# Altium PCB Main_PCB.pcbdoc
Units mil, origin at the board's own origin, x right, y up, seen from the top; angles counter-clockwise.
Board outline 4486.01 x 2606.73 mil, 2 copper layers (Top Layer, Bottom Layer); 37 components, 31 nets, 178 pads, 21 vias.
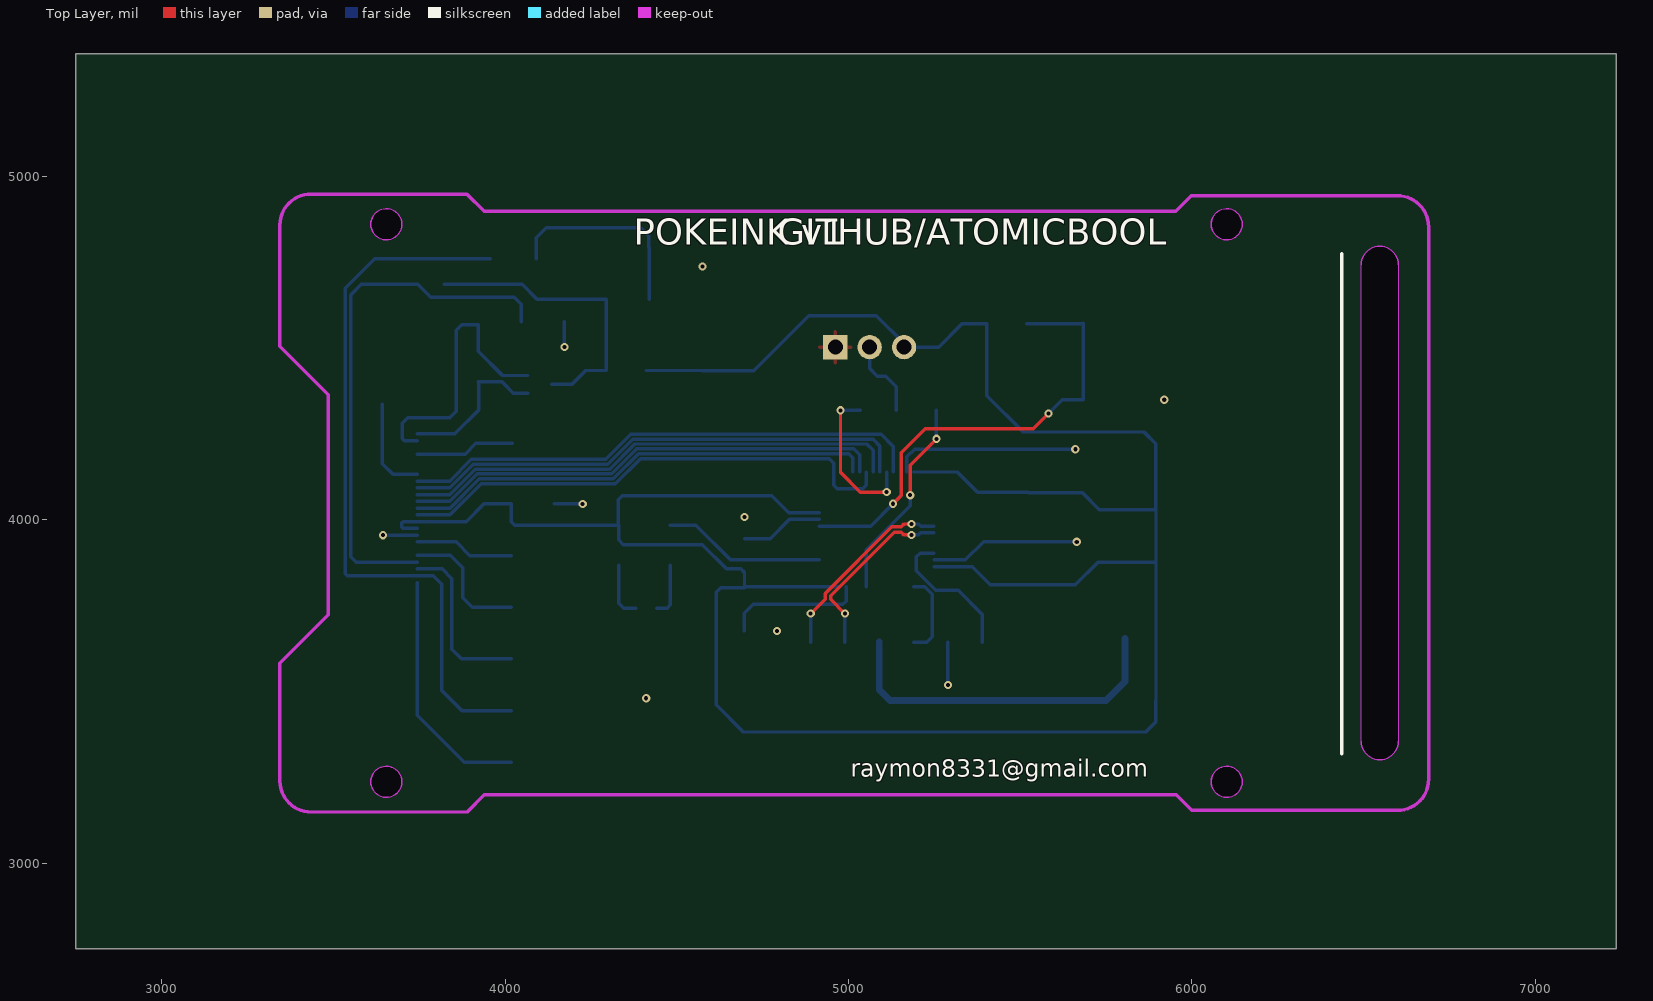
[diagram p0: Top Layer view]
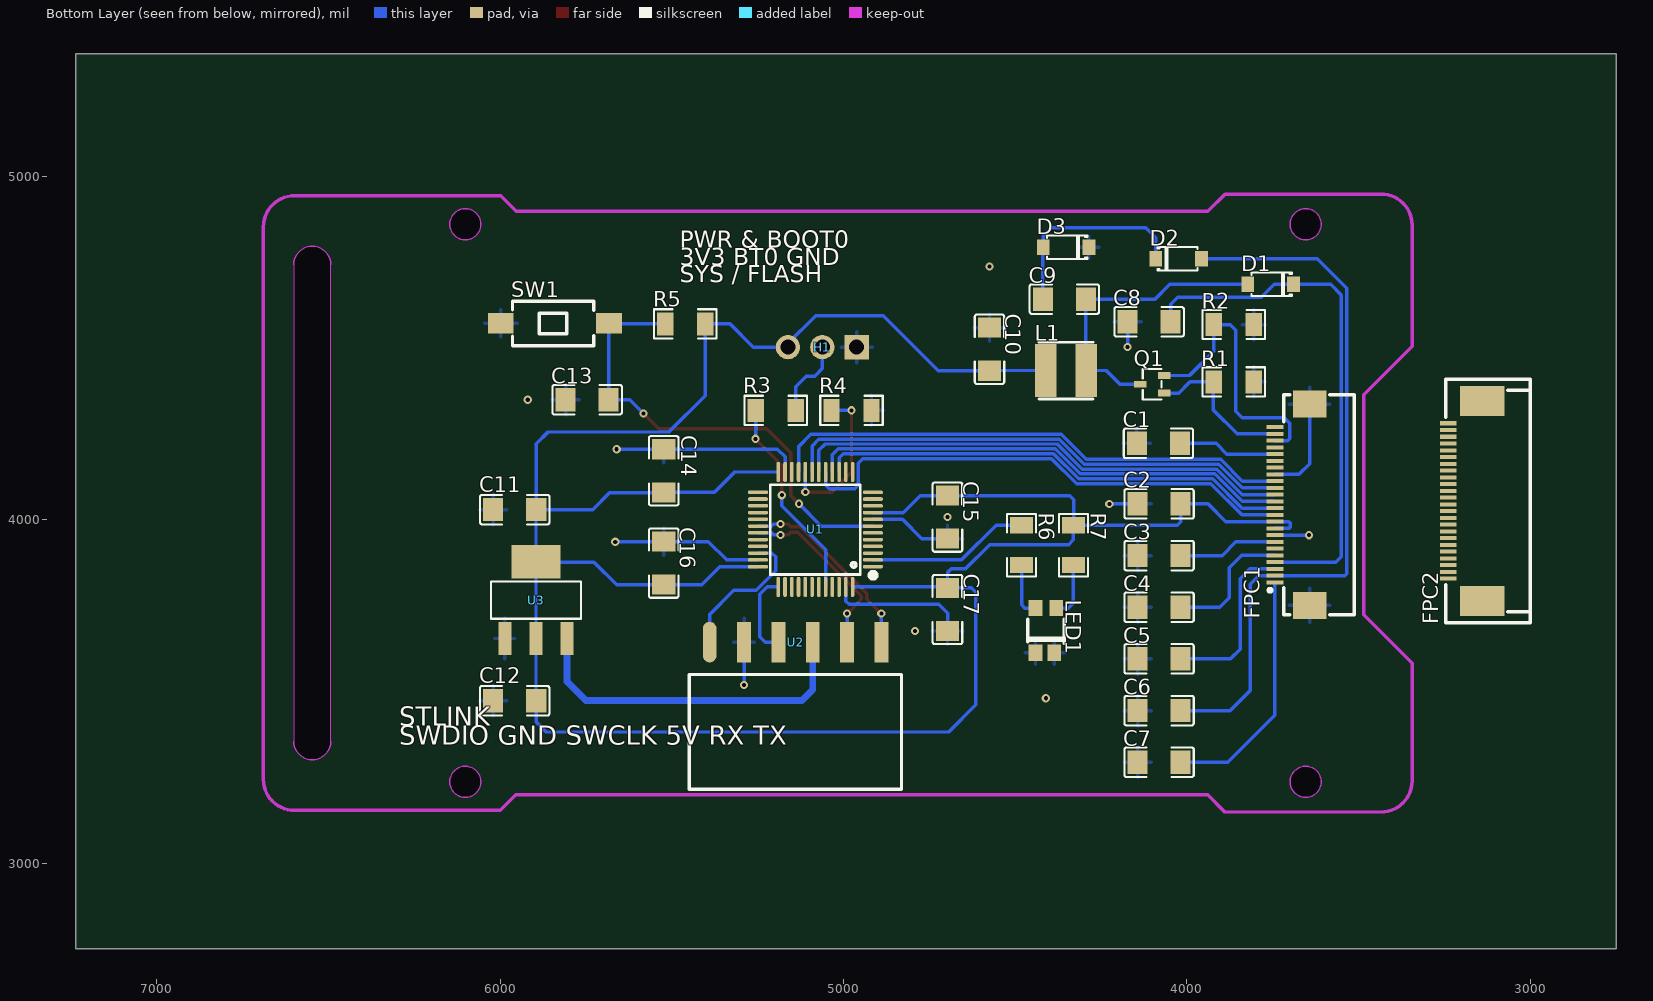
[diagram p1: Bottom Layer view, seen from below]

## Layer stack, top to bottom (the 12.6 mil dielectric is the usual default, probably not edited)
Top Layer: signal copper (thickness not stored)
Dielectric: dielectric 12.6, FR-4, Dk 4.8
Bottom Layer: signal copper (thickness not stored)

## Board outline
7236.01,2750 2750,2750 2750,5356.73 7236.01,5356.73
cut-out: 3699.25,4860.64 cw(c3653.98,4860.64) 3608.7,4860.64 cw(c3653.98,4860.64)
cut-out: 3699.25,3236.64 cw(c3653.98,3236.64) 3608.7,3236.64 cw(c3653.98,3236.64)
cut-out: 6147.24,4860.64 cw(c6101.96,4860.64) 6056.69,4860.64 cw(c6101.96,4860.64)
cut-out: 6147.24,3236.64 cw(c6101.96,3236.64) 6056.69,3236.64 cw(c6101.96,3236.64)
cut-out: 6547.71,4796.67 cw(c6547.71,4742.54) 6601.85,4742.54 6601.85,3354.74 cw(c6547.71,3354.74) 6547.71,3300.61 cw(c6547.71,3354.74) 6493.58,3354.74 6493.58,4742.54 cw(c6547.71,4742.54)

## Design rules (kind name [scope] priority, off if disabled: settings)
BoardOutlineClearance copperThickness1oz [All] p0: genericclearance=10 ignorepadtopadclearanceinfootprint=FALSE except(0: Arc-SplitContinuation Track-SplitContinuation SMDPad-SplitContinuation THPad-SplitContinuation Via-SplitContinuation Fill-SplitContinuation Poly-SplitContinuation Region-SplitContinuation Text-SplitContinuation; 6: Track-CutoutEdge SMDPad-CutoutEdge THPad-CutoutEdge Via-CutoutEdge Region-CutoutEdge; 11.8: Track-OutlineEdge SMDPad-OutlineEdge THPad-OutlineEdge Via-OutlineEdge Fill-OutlineEdge Region-OutlineEdge Poly-OutlineEdge Text-OutlineEdge Fill-CutoutEdge)
BoardOutlineClearance copperThickness2oz [All] p0: genericclearance=10 ignorepadtopadclearanceinfootprint=FALSE except(0: Arc-SplitContinuation Track-SplitContinuation SMDPad-SplitContinuation THPad-SplitContinuation Via-SplitContinuation Fill-SplitContinuation Poly-SplitContinuation Region-SplitContinuation Text-SplitContinuation; 6: Track-CutoutEdge SMDPad-CutoutEdge THPad-CutoutEdge Via-CutoutEdge Region-CutoutEdge; 11.8: Track-OutlineEdge SMDPad-OutlineEdge THPad-OutlineEdge Via-OutlineEdge Fill-OutlineEdge Region-OutlineEdge Poly-OutlineEdge Text-OutlineEdge Fill-CutoutEdge)
Clearance copperThickness1oz [(InNet('VCOM') OR InNet('PVGL') OR InNet('$1N1662') OR InNet('PVGH') OR InNet('$1N1618') OR InNet('$1N1584') OR InNet('GND') OR InNet('3V3') OR InNet('CS') OR InNet('DCX') OR InNet('RES') OR InNet('BUSY') OR InNet('$1N1465') OR InNet('RESE') OR InNet('GDR') OR InNet('$1N1889') OR InNet('$1N2921') OR InNet('NRST') OR InNet('BOOT1') OR InNet('BOOT0') OR InNet('$1N4223') OR InNet('5V') OR InNet('SDA') OR InNet('SCK') OR InNet('USART_TX') OR InNet('USART_RX') OR InNet('SWDIO') OR InNet('SWCLK') OR InNet('LED_MCU') OR InNet('$1N6084') OR InNet('$1N6080'))] p1: gap=7 ignorepadtopadclearanceinfootprint=FALSE except(4: Track-Track; 6: Track-SMDPad SMDPad-SMDPad Track-THPad SMDPad-THPad THPad-THPad Track-Via SMDPad-Via THPad-Via Via-Via SMDPad-Fill THPad-Fill Via-Fill Fill-Fill Track-Region SMDPad-Region THPad-Region Via-Region Region-Region Track-Poly SMDPad-Poly THPad-Poly Via-Poly Fill-Poly Region-Poly Poly-Poly Track-Text SMDPad-Text THPad-Text Via-Text Fill-Text Region-Text Poly-Text Text-Text; 6.9: Track-Hole SMDPad-Hole THPad-Hole Via-Hole Fill-Hole Region-Hole Poly-Hole Text-Hole Sheet-Hole; 11.8: Track-Fill Fill-Region Track-Sheet SMDPad-Sheet THPad-Sheet Via-Sheet Fill-Sheet Region-Sheet Poly-Sheet Text-Sheet)
Clearance copperThickness2oz [All] p1: gap=7 ignorepadtopadclearanceinfootprint=FALSE except(6: Track-SMDPad SMDPad-SMDPad Track-THPad SMDPad-THPad THPad-THPad Track-Via SMDPad-Via THPad-Via Via-Via SMDPad-Fill THPad-Fill Via-Fill Fill-Fill Track-Region SMDPad-Region THPad-Region Via-Region Region-Region Track-Poly SMDPad-Poly THPad-Poly Via-Poly Fill-Poly Region-Poly Poly-Poly Track-Text SMDPad-Text THPad-Text Via-Text Fill-Text Region-Text Poly-Text Text-Text; 6.9: Track-Hole SMDPad-Hole THPad-Hole Via-Hole Fill-Hole Region-Hole Poly-Hole Text-Hole Sheet-Hole; 8: Track-Track; 11.8: Track-Fill Fill-Region Track-Sheet SMDPad-Sheet THPad-Sheet Via-Sheet Fill-Sheet Region-Sheet Poly-Sheet Text-Sheet)
DiffPairsRouting differentialPair [All] p1: maxuncoupledlength=200 minlimit=6 maxlimit=6 mostfreqgap=6 toplayer_minwidth=5 toplayer_prefwidth=10 toplayer_maxwidth=100 bottomlayer_minwidth=5 bottomlayer_prefwidth=10 bottomlayer_maxwidth=100
PasteMaskExpansion pasteMaskExpansion [All] p1: expansion=0
PlaneConnect innerPlane [All] p1: planeconnectstyle=Relief reliefexpansion=20 reliefentries=4 reliefconductorwidth=10 reliefairgap=10
PolygonConnect copperRegion [All] p1: connectstyle=Relief reliefentries=4 reliefconductorwidth=10 polygonreliefangle="90 Angle" airgapwidth=10
RoutingVias viaSize [All] p1: viastyle="Through Hole" holewidth=12.0078 minholewidth=11.811 maxholewidth=248.0314 width=24.0158 minwidth=19.685 maxwidth=393.7008
SolderMaskExpansion solderMaskExpansion [All] p1: useseparateexpansions=TRUE expansion=2 expansionbottom=2
Width copperThickness1oz [All] p1: maxlimit=100 minlimit=5 preferedwidth=10
Width copperThickness2oz [All] p1: maxlimit=100 minlimit=8 preferedwidth=10

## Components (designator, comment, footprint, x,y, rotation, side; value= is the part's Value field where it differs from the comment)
C1 "CL31B105KAHNNNE" C1206 4082.98,4222.64 r180 bottom
C2 "CL31B105KAHNNNE" C1206 4080.98,4046.14 r0 bottom
C3 "CL31B105KAHNNNE" C1206 4080.98,3895.64 r0 bottom
C4 "CL31B105KAHNNNE" C1206 4080.98,3745.14 r0 bottom
C5 "CL31B105KAHNNNE" C1206 4080.98,3594.64 r0 bottom
C6 "CL31B105KAHNNNE" C1206 4080.98,3444.14 r0 bottom
C7 "CL31B105KAHNNNE" C1206 4080.98,3293.64 r0 bottom
C8 "CL31B105KAHNNNE" C1206 4109.98,4576.64 r180 bottom
C9 "1206B475K250NT" C1206 4356.98,4642.64 r0 bottom
C10 "1206B475K250NT" C1206 4574.98,4496.64 r90 bottom
C11 "CL31B104KCFNNNE" C1206 5957.98,4029.64 r180 bottom
C12 "CL31B104KCFNNNE" C1206 5957.98,3472.64 r180 bottom
C13 "CL31B104KCFNNNE" C1206 5746.98,4349.64 r0 bottom
C14 "CL31B104KCFNNNE" C1206 5523.98,4142.64 r270 bottom
C15 "CL31B104KCFNNNE" C1206 4697.39,4007.64 r90 bottom
C16 "CL31B104KCFNNNE" C1206 5523.98,3873.64 r270 bottom
C17 "CL31B104KCFNNNE" C1206 4697.39,3738.64 r270 bottom
D1 "MBR0530_C77336" SOD-123_L2.8-W1.8-LS3.7-RD 3755.98,4685.64 r0 bottom
D2 "MBR0530_C77336" SOD-123_L2.8-W1.8-LS3.7-RD 4023.98,4760.64 r180 bottom
D3 "MBR0530_C77336" SOD-123_L2.8-W1.8-LS3.7-RD 4351.98,4793.64 r0 bottom
FPC1 "FPC-05F-24PH20" FPC-SMD_24P-P0.50_FPC-05F-24PH20 3692.98,4043.64 r90 bottom
FPC2 "AFC07-S24ECA-00" FPC-SMD_AFC07-S24ECA-00 3188.98,4054.64 r90 bottom
H1 "PZ254R-11-03P" HDR-TH_3P-P2.54-H-M-W10.4 5061.98,4502.64 r0 bottom
L1 "FNR4020S680MT" IND-SMD_L4.0-W4.0_FNR40XXS 4351.98,4434.64 r180 bottom
LED1 "TJ-S3227SW1TCGLC2R6B-A5" LED-SMD_4P-L3.2-W2.7_PD15-22C 4410.98,3677.64 r90 bottom
Q1 "SI1308EDL" SOT-323-3_L2.0-W1.3-P1.30-LS2.1-BR 4100.98,4394.64 r180 bottom
R1 "FRC1206J105 TS" R1206 3863.92,4401.64 r0 bottom
R2 "FRC1206J2R2 TS" R1206 3863.92,4568.37 r0 bottom
R3 "FRC1206J103 TS" R1206 5197.98,4318.64 r180 bottom
R4 "FRC1206J103 TS" R1206 4976.98,4318.64 r180 bottom
R5 "FRC1206J103 TS" R1206 5460.98,4570.64 r180 bottom
R6 "FRC1206J102 TS" R1206 4481.48,3926.14 r270 bottom
R7 "FRC1206J102 TS" R1206 4330.48,3926.14 r270 bottom
SW1 "TS-1101-C-W" SW-SMD_L6.0-W3.3-LS8.0 5840.98,4572.64 r180 bottom
U1 "STM32F103C8T6" LQFP-48_L7.0-W7.0-P0.50-LS9.0-BL 5081.98,3971.64 r90 bottom
U2 "HX PM2.54-1x6P WT" HDR-SMD_6P-P2.54-H-F-W11.7 5139.98,3643.64 r180 bottom
U3 "AMS1117-3.3_C347222" SOT-223-4_L6.5-W3.5-P2.30-LS7.0-BR 5895.98,3765.64 r270 bottom

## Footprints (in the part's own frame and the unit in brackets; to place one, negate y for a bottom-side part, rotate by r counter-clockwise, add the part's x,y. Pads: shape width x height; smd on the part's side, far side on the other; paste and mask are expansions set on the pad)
C1206 [mm]
  rect 1.485x1.728 smd: 1(-1.593,0) 2(1.593,0)
  silkscreen extent -2.56,-1.09 2.56,1.09
FPC-SMD_24P-P0.50_FPC-05F-24PH20 [mm]
  rect 0.3x1.25 smd: 1(5.75,1.288) 2(5.25,1.288) 3(4.75,1.288) 4(4.25,1.288) 5(3.75,1.288) 6(3.25,1.288) 7(2.75,1.288) 8(2.25,1.288) 9(1.75,1.288) 10(1.25,1.288) 11(0.75,1.288) 12(0.25,1.288) 13(-0.25,1.288) 14(-0.75,1.288) 15(-1.25,1.288) 16(-1.75,1.288) 17(-2.25,1.288) 18(-2.75,1.288) 19(-3.25,1.288) 20(-3.75,1.288) 21(-4.25,1.288) 22(-4.75,1.288) 23(-5.25,1.288) 24(-5.75,1.288)
  rect 2x2.5 smd: 25(7.44,-1.288) 26(-7.44,-1.288)
  silkscreen extent -8.13,-4.57 8.13,1.78
FPC-SMD_AFC07-S24ECA-00 [mm]
  rect 0.3x1.2 smd: 1(5.75,1.266) 2(5.251,1.266) 3(4.75,1.266) 4(4.25,1.266) 5(3.75,1.266) 6(3.249,1.266) 7(2.749,1.266) 8(2.25,1.266) 9(1.751,1.266) 10(1.25,1.266) 11(0.75,1.266) 12(0.25,1.266) 13(-0.251,1.266) 14(-0.75,1.266) 15(-1.25,1.266) 16(-1.749,1.266) 17(-2.25,1.266) 18(-2.75,1.266) 19(-3.251,1.266) 20(-3.751,1.266) 21(-4.251,1.266) 22(-4.749,1.266) 23(-5.25,1.266) 24(-5.75,1.266)
  rect 2.2x3.3 smd: 25(-7.401,-1.266) 26(7.401,-1.259)
  silkscreen extent -9,-4.8 9,1.46
HDR-SMD_6P-P2.54-H-F-W11.7 [mm]
  oval 1.02x3 smd: 1(-6.35,0)
  rect 1.02x3 smd: 2(-3.81,0) 3(-1.27,0) 4(1.27,0) 5(3.81,0) 6(6.35,0)
  silkscreen extent -7.87,-10.9 7.84,-2.4
HDR-TH_3P-P2.54-H-M-W10.4 [mm]
  rect 1.8x1.8 hole 1.1: 1(-2.54,0)
  round 1.8 hole 1.1: 2(0,0) 3(2.54,0)
IND-SMD_L4.0-W4.0_FNR40XXS [mm]
  rect 1.6x3.9 smd: 1(-1.5,0) 2(1.5,0)
  silkscreen extent -2,-2.1 2,2.1
LED-SMD_4P-L3.2-W2.7_PD15-22C [mm]
  rect 1.2x1 smd: 1(-1.65,-0.636) 2(1.65,-0.763) 3(1.65,0.764) 4(-1.65,0.764)
  silkscreen extent -0.97,-1.35 0.84,1.35
LQFP-48_L7.0-W7.0-P0.50-LS9.0-BL [mm]
  oval 0.27x1.5 smd: 1(-2.75,-4.25) 2(-2.25,-4.25) 3(-1.75,-4.25) 4(-1.25,-4.25) 5(-0.75,-4.25) 6(-0.25,-4.25) 7(0.25,-4.25) 8(0.75,-4.25) 9(1.25,-4.25) 10(1.75,-4.25) 11(2.25,-4.25) 12(2.75,-4.25) 25(2.75,4.25) 26(2.25,4.25) 27(1.75,4.25) 28(1.25,4.25) 29(0.75,4.25) 30(0.25,4.25) 31(-0.25,4.25) 32(-0.75,4.25) 33(-1.25,4.25) 34(-1.75,4.25) 35(-2.25,4.25) 36(-2.75,4.25)
  oval 1.5x0.27 smd: 13(4.25,-2.75) 14(4.25,-2.25) 15(4.25,-1.75) 16(4.25,-1.25) 17(4.25,-0.75) 18(4.25,-0.25) 19(4.25,0.25) 20(4.25,0.75) 21(4.25,1.25) 22(4.25,1.75) 23(4.25,2.25) 24(4.25,2.75) 37(-4.25,2.75) 38(-4.25,2.25) 39(-4.25,1.75) 40(-4.25,1.25) 41(-4.25,0.75) 42(-4.25,0.25) 43(-4.25,-0.25) 44(-4.25,-0.75) 45(-4.25,-1.25) 46(-4.25,-1.75) 47(-4.25,-2.25) 48(-4.25,-2.75)
  silkscreen extent -3.59,-4.46 3.3,3.34
R1206 [mil]
  rect 47.54x66.97 smd: 1(-58.22,0) 2(58.22,0)
  silkscreen extent -91,-42 91,42
SOD-123_L2.8-W1.8-LS3.7-RD [mm]
  rect 0.95x1.15 smd: 1(-1.692,0) 2(1.692,0)
  silkscreen extent -1.58,-0.87 1.41,0.87
SOT-223-4_L6.5-W3.5-P2.30-LS7.0-BR [mm]
  rect 2.47x0.98 smd: 1(2.835,-2.3) 2(2.835,0) 3(2.835,2.3)
  rect 2.47x3.6 smd: 4(-2.835,0)
  silkscreen extent -1.37,-3.33 1.37,3.33
SOT-323-3_L2.0-W1.3-P1.30-LS2.1-BR [mm]
  rect 0.936x0.5 smd: 1(0.898,-0.65) 2(0.898,0.65) 3(-0.898,0)
  silkscreen extent -0.7,-1.13 0.7,1.13
SW-SMD_L6.0-W3.3-LS8.0 [mm]
  rect 1.9x1.5 smd: 1(-4,0) 2(4,0)
  silkscreen extent -3.14,-1.67 2.86,1.63

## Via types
v1: diameter 24.02, hole 12.01, Top Layer to Bottom Layer, 21 vias

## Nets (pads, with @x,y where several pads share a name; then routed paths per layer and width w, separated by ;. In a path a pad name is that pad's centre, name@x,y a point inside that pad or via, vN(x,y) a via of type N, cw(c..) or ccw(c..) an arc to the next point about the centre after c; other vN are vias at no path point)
3V3: C2.1 C10.1 C11.2 C12.2 C14.2 C15.2 C16.2 C17.1 FPC1.15 FPC1.16 H1.3 L1.1 R5.2 R7.1 U1.9 U1.24 U1.36 U1.48 U3.2 U3.4 | length 8115.3
  Bottom Layer w10: FPC1.16@3743.99,3974.73 3701.88,3974.73 3698.98,3977.64 3698.98,3990.64 3702.76,3994.42 FPC1.15 3886.76,3994.42 3938.48,4046.14 C2.1 4017.98,4045.84 4017.98,3994.64 4028.26,3984.36 R7.1 ; L1.1 4574.28,4434.64 C10.1 4724.28,4433.94 4884.98,4594.64 5080.98,4594.64 5161.98,4513.64 H1.3 5262.98,4502.64 5330.98,4570.64 R5.2 5402.98,4570.42 5402.98,4361.64 5508.98,4255.64 5860.98,4255.64 5895.28,4221.34 C11.2 ; U1.9 4826.77,4020.85 4777.28,4070.34 C15.2 4341.68,4070.34 4329.98,4058.64 4329.98,3984.86 R7.1 ; U1.48 4700.37,3804.32 C17.1 ; U1.24 5316.66,4138.96 5375.98,4079.64 5523.68,4079.64 C14.2 5525.28,4078.64 5681.98,4078.64 5730.98,4029.64 C11.2 ; U1.36 5360.25,3863.37 5412.68,3810.94 C16.2 5661.28,3810.94 5726.98,3876.64 5895.37,3876.64 U3.4 ; R7.1 4330.48,3941.14 4343.98,3927.64 4573.98,3927.64 4644.98,3856.64 4686.98,3856.64 4697.39,3846.23 C17.1 ; C17.1 4627.68,3801.34 4614.98,3788.64 4614.98,3460.64 4693.98,3381.64 5865.98,3381.64 5895.28,3410.94 C12.2 5895.98,3473.34 U3.2 U3.4 ; C11.2 5895.98,4028.94 U3.4
5V: U2.4 U3.3 | length 1015.8
  Bottom Layer w20: U2.4 5089.98,3504.64 5120.98,3473.64 5750.98,3473.64 5805.43,3528.09 U3.3
$1N1465: C1.2 FPC1.5 | length 289.3
  Bottom Layer w10: FPC1.5@3743.99,4191.27 3883.61,4191.27 3914.98,4222.64 C1.2
$1N1584: C3.1 FPC1.18 | length 290.7
  Bottom Layer w10: FPC1.18@3743.99,3935.36 3857.25,3935.36 3896.98,3895.64 C3.1
$1N1618: C4.1 FPC1.20 | length 387.7
  Bottom Layer w10: FPC1.20@3743.99,3895.99 3840.62,3895.99 3876.98,3859.64 3876.98,3772.64 3904.48,3745.14 C4.1
$1N1662: C5.1 FPC1.22 | length 503.5
  Bottom Layer w10: FPC1.22@3744,3856.64 3816.98,3856.64 3844.98,3828.64 3844.98,3622.64 3872.98,3594.64 C5.1
$1N1889: C9.2 D2.1 D3.2 | length 595.4
  Bottom Layer w10: D2.1 4090.61,4821.27 4119.98,4850.64 4394.98,4850.64 4418.61,4827.01 D3.2 4419.68,4792.57 C9.2
$1N2921: C9.1 D1.2 L1.2 Q1.3 | length 871.2
  Bottom Layer w10: D1.2 4049.98,4685.64 4092.98,4642.64 C9.1 4294.28,4436 L1.2 4234.98,4434.64 4194.98,4394.64 Q1.3
$1N4223: H1.2 R3.2 | length 230.3
  Bottom Layer w10: H1.2 5061.98,4440.64 5084.25,4418.36 5108.25,4418.36 5139.76,4386.86 R3.2
$1N6080: LED1.2 R7.2 | length 167.2
  Bottom Layer w10: R7.2 4330.98,3867.42 4330.98,3756.64 4345.02,3742.6 LED1.2
$1N6084: LED1.3 R6.2 | length 160.1
  Bottom Layer w10: LED1.3 4471.94,3742.6 ; 4471.98,3742.64 4481.48,3752.14 R6.2
BOOT0: R3.1 U1.44 | length 599.4
  Top Layer w10: v1(5179.98,4071.64) 5179.98,4158.64 v1(5256.98,4235.64)
  Bottom Layer w10: U1.44 5052.45,3913.11 5179.98,4040.64 v1(5179.98,4071.64) ; R3.1 5256.2,4236.42 v1(5256.98,4235.64)
BOOT1: R4.1 U1.20 | length 453.1
  Top Layer w10: v1(4976.98,4318.64) 4976.98,4138.64 5034.98,4080.64 v1(5111.51,4080.64)
  Bottom Layer w10: v1@4978.98,4318.64 R4.1 ; v1(5111.51,4080.64) U1.20
BUSY: FPC1.9 U1.21 | length 1532.6
  Bottom Layer w10: FPC1.9@3743.99,4112.53 3838.87,4112.53 3901.98,4175.64 4292.98,4175.64 4365.98,4248.64 5095.98,4248.64 5131.19,4213.43 U1.21
CS: FPC1.12 U1.16 | length 1410
  Bottom Layer w10: FPC1.12@3743.99,4053.47 3839.27,4053.47 3919.39,4133.59 4310.39,4133.59 4383.39,4206.59 5015.98,4206.59 5032.77,4189.8 U1.16
DCX: FPC1.11 U1.18 | length 1460.2
  Bottom Layer w10: FPC1.11@3743.99,4073.16 3839.14,4073.16 3913.59,4147.61 4304.59,4147.61 4377.59,4220.61 5053.98,4220.61 5072.14,4202.45 U1.18
GDR: FPC1.2 Q1.1 R1.2 | length 447
  Bottom Layer w10: FPC1.2@3743.99,4250.33 3853.67,4250.33 3922.98,4319.64 3922.98,4400.8 R1.2 3990.98,4401.64 4023.57,4369.05 Q1.1
GND: C1.1 C2.2 C3.2 C4.2 C5.2 C6.2 C7.2 C8.1 C10.2 C11.1 C12.1 C13.2 C14.1 C15.1 C16.1 C17.2 D3.1 FPC1.8 FPC1.17 FPC1.25 FPC1.26 H1.1 LED1.1 LED1.4 R1.1 R2.1 R4.2 SW1.1 U1.8 U1.23 U1.35 U1.47 U2.2 U3.1 | length 2295.4
  Bottom Layer w10: FPC1.25@3642.61,4336.55 3641.98,4335.92 3641.98,4163.64 3673.39,4132.22 FPC1.8@3743.99,4132.22 ; v1(3643.98,3955.05) FPC1.17@3743.99,3955.05 ; C2.2 v1(4225.98,4046.14) ; v1(4172.67,4503.42) C8.1 ; C17.2 4696.98,3676.35 4696.98,3727.64 4722.98,3753.64 4983.98,3753.64 4993.4,3763.06 U1.47 ; C15.1 4772.28,3944.94 4828.51,4001.17 U1.8 ; U1.23 5170.56,4183.22 5192.68,4205.34 C14.1 v1(5661.05,4205.34) ; U1.35 5340.4,3883.06 5393.68,3936.34 C16.1 5664.28,3936.34 v1(5664.98,3935.64) ; v1(5289.98,3518.64) U2.2
  other v1: 4410.98,3479.91 4791.81,3675.94 4697.39,4007.64 5919.98,4349.64 4574.98,4737.64
LED_MCU: R6.1 U1.2 | length 475.1
  Bottom Layer w10: R6.1 4555.26,3984.36 4656.56,3883.06 U1.2
NRST: C13.1 R5.1 SW1.2 U1.7 | length 1383.2
  Top Layer w10: v1(5129.98,4046.64) 5153.98,4070.64 5153.98,4194.64 5223.98,4264.64 5537.98,4264.64 v1(5582.98,4309.64)
  Bottom Layer w10: U1.7 5064.82,3981.48 v1(5129.98,4046.64) ; R5.1 5681.5,4570.64 SW1.2 5684.28,4571.86 C13.1 5622.98,4349.64 v1(5582.98,4309.64)
PVGH: C8.2 D1.1 FPC1.21 | length 1547.8
  Bottom Layer w10: FPC1.21@3743.99,3876.31 3566.3,3876.31 3549.98,3892.64 3549.98,4654.64 3580.98,4685.64 D1.1 3744.98,4685.64 3782.98,4647.64 4026.98,4647.64 4047.28,4627.34 C8.2
PVGL: C6.1 D2.2 FPC1.23 | length 2121.4
  Bottom Layer w10: D2.2 3619.98,4760.64 3533.98,4674.64 3533.98,3842.64 3539.67,3836.94 FPC1.23 3790.67,3836.94 3815.98,3811.64 3815.98,3502.64 3874.48,3444.14 C6.1
RES: FPC1.10 U1.19 | length 1490.6
  Bottom Layer w10: FPC1.10@3743.99,4092.85 3839.01,4092.85 3907.78,4161.62 4298.78,4161.62 4371.78,4234.62 5071.99,4234.62 5091.82,4214.8 U1.19
RESE: FPC1.3 Q1.2 R2.2 | length 820.6
  Bottom Layer w10: FPC1.3@3743.99,4230.64 3705.97,4230.64 3699.98,4236.64 3699.98,4280.64 3715.98,4296.64 3838.98,4296.64 3857.98,4315.64 3857.98,4551.64 3873.98,4567.64 3921.4,4567.64 R2.2 3922.14,4490.48 3992.39,4420.23 Q1.2
SCK: FPC1.13 U1.15 | length 1380.9
  Bottom Layer w10: FPC1.13@3743.99,4033.79 3839.42,4033.79 3924.62,4119 4315.62,4119 4388.62,4192 5001.62,4192 5013.08,4180.54 U1.15
SDA: FPC1.14 U1.17 | length 1491.9
  Bottom Layer w10: FPC1.14@3743.99,4014.1 3839.55,4014.1 3930.42,4104.98 4321.42,4104.98 4394.42,4177.98 4943.63,4177.98 4957.41,4164.21 4957.41,4100.64 4967.41,4090.64 5041.98,4090.64 5052.45,4101.11 U1.17
SWCLK: U1.37 U2.3 | length 246.6
  Bottom Layer w10: U2.3 5227.98,3643.64 5243.98,3659.64 5243.98,3783.01 5222.67,3804.32 U1.37
SWDIO: U1.34 U2.1 | length 421.2
  Bottom Layer w10: U1.34 5209.08,3902.74 5197.98,3891.64 5197.98,3851.64 5254.98,3794.64 5319.41,3794.64 5389.98,3724.07 U2.1
USART_RX: U1.31 U2.5 | length 536.2
  Top Layer w10: v1(4989.98,3726.54) 4947.98,3768.54 4947.98,3778.54 5133.08,3963.64 5153.97,3963.64 5161.97,3955.64 v1(5183.98,3955.64)
  Bottom Layer w10: U2.5 v1(4989.98,3726.54) ; v1(5183.98,3955.64) 5202.98,3955.64 5209.14,3961.8 U1.31
USART_TX: U1.30 U2.6 | length 562.7
  Top Layer w10: v1(4889.98,3726.54) 4931.98,3768.54 4931.98,3785.16 5126.45,3979.64 5153.97,3979.64 5161.97,3987.64 v1(5183.98,3987.64)
  Bottom Layer w10: U2.6 v1(4889.98,3726.54) ; v1(5183.98,3987.64) 5203.98,3987.64 5210.14,3981.48 U1.30
VCOM: C7.1 FPC1.24 | length 717.7
  Bottom Layer w10: FPC1.24@3743.99,3817.25 3743.99,3430.63 3880.98,3293.64 C7.1
pads on no net: FPC1.1 FPC1.4 FPC1.6 FPC1.7 FPC1.19 FPC2.1 FPC2.2 FPC2.3 FPC2.4 FPC2.5 FPC2.6 FPC2.7 FPC2.8 FPC2.9 FPC2.10 FPC2.11 FPC2.12 FPC2.13 FPC2.14 FPC2.15 FPC2.16 FPC2.17 FPC2.18 FPC2.19 FPC2.20 FPC2.21 FPC2.22 FPC2.23 FPC2.24 FPC2.25 FPC2.26 U1.1 U1.3 U1.4 U1.5 U1.6 U1.10 U1.11 U1.12 U1.13 U1.14 U1.22 U1.25 U1.26 U1.27 U1.28 U1.29 U1.32 U1.33 U1.38 U1.39 U1.40 U1.41 U1.42 U1.43 U1.45 U1.46

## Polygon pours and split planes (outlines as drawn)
GND on Top Layer (solid, remove dead copper, pour order 0): 3241.76,5106.73 6986.01,5106.73 6986.01,3093.73 3241.76,3093.73
GND on Bottom Layer (solid, remove dead copper, pour order 2): 3191.67,5013 6889.65,5013 6889.65,3000 3191.67,3000

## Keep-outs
Board Outline Layer:
  circle w1: c3653.98,4860.64 r45.28
  region: 3699.25,4860.64 cw(c3653.98,4860.64) 3608.7,4860.64 cw(c3653.98,4860.64)
  circle w1: c3653.98,3236.64 r45.28
  region: 3699.25,3236.64 cw(c3653.98,3236.64) 3608.7,3236.64 cw(c3653.98,3236.64)
  circle w1: c6101.96,4860.64 r45.28
  region: 6147.24,4860.64 cw(c6101.96,4860.64) 6056.69,4860.64 cw(c6101.96,4860.64)
  circle w1: c6101.96,3236.64 r45.28
  region: 6147.24,3236.64 cw(c6101.96,3236.64) 6056.69,3236.64 cw(c6101.96,3236.64)
  region: 6547.71,4796.67 cw(c6547.71,4742.54) 6601.85,4742.54 6601.85,3354.74 cw(c6547.71,3354.74) 6547.71,3300.61 cw(c6547.71,3354.74) 6493.58,3354.74 6493.58,4742.54 cw(c6547.71,4742.54)
  lines w1: 6493.58,3354.74 ccw(c6547.71,3354.74) 6547.71,3300.61 ccw(c6547.71,3354.74) 6601.85,3354.74 6601.85,4742.54 ccw(c6547.71,4742.54) 6547.71,4796.67 ccw(c6547.71,4742.54) 6493.58,4742.54 6493.58,3354.74
  lines w10: 3343.98,4858.32 3343.98,4504.87 3485.21,4363.64 3485.21,3723.64 3343.98,3582.41 3343.98,3238.64 ccw(c3434.53,3239.25) 3435.15,3148.7 3889.62,3148.7 3939.56,3198.64 5954.56,3198.64 5999.56,3153.64 6369.27,3153.67 6599.59,3153.67 ccw(c6599.94,3243.89) 6690.17,3243.54 ; 3343.98,4858.64 cw(c3434.24,4858.32) 3434.56,4948.58 3889.04,4948.58 3938.98,4898.64 5953.98,4898.64 5998.98,4943.64 6368.68,4943.61 6599.01,4943.61 cw(c6599.65,4853.09) 6690.17,4853.73 ; 6690.43,3243.54 6690.43,4853.73

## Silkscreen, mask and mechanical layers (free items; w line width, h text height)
Top Silkscreen Layer:
  lines w10: 6436.64,3318.64 6436.64,4775.33
  text "POKEINK v1" at 4374.98,4800.64 h75
  text "GITHUB/ATOMICBOOL" at 4793.98,4800.64 h75
  text "raymon8331@gmail.com" at 5006.98,3251.64 h50
Bottom Silkscreen Layer:
  text "PWR & BOOT0" at 5477.98,4791.64 h50
  text "3V3 BT0 GND" at 5477.98,4741.64 h50
  text "SYS / FLASH" at 5477.98,4691.64 h50
  text "STLINK" at 6294.98,3399.64 h55
  text "SWDIO GND SWCLK 5V RX TX" at 6294.98,3344.64 h55
Mechanical Layer:
  circle w1: c3653.98,4860.64 r45.28
  circle w1: c3653.98,3236.64 r45.28
  circle w1: c6101.96,4860.64 r45.28
  circle w1: c6101.96,3236.64 r45.28
  lines w1: 6493.58,3354.74 ccw(c6547.71,3354.74) 6547.71,3300.61 ccw(c6547.71,3354.74) 6601.85,3354.74 6601.85,4742.54 ccw(c6547.71,4742.54) 6547.71,4796.67 ccw(c6547.71,4742.54) 6493.58,4742.54 6493.58,3354.74
Mech6:
  circle w10: c3653.98,4860.64 r61.02
  circle w10: c3653.98,3236.64 r61.02
  circle w10: c6101.96,4860.64 r61.02
  circle w10: c6101.96,3237.64 r61.02
  lines w10: 3354.83,3318.64 6465.07,3318.64 6465.07,4775.33 3354.83,4775.33 3354.83,3318.64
